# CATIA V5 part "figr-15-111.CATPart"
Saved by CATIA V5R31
Part number: Part1
Bounding box of the stored display mesh (mm): x 0.737 to 206.429, y 0 to 112.04, z -6 to 2
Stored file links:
  D:\PROJECTS\Project 2021\US EDITION\CATIA V5 6R 2021\Resources\Part Files\c15_catia_v5_6r2021_prt\figr-15-111.CATPart
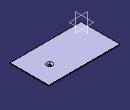
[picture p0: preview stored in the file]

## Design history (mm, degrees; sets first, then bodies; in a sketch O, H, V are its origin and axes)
SheetMetalParameters1: Thickness 2, BendRadius 4, KFactor 0.400515 {= log(min(100,max(20*SheetMetalParameters1.BendRadius,SheetMetalParameters1.Thickness)/SheetMetalParameters1.Thickness))/log(100)/2}, ReliefRadialLength 1, ReliefAxialLength 2, MinimumBendRadius 0
Body1 (main body)
  Sketch1 on xy-plane, origin (0, 0, 0), H (1, 0, 0), V (0, 1, 0)
    line L1 (0.7372, 112.0403) -> (206.4285, 112.0403)
    line L2 (206.4285, 112.0403) -> (206.4285, 0)
    line L3 (206.4285, 0) -> (0.7372, 0)
    line L4 (0.7372, 0) -> (0.7372, 112.0403)
    horizontal: L1 H, L3 H
    vertical: L2 V, L4 V
  Wall1: Thickness 2, Profile Sketch1, OffsetValue 0
  Sketch2 on face of Wall1, origin (152.409, 60.7083, 2), H (1, 0, 0), V (0, 1, 0)
    point P1 (0, 0)
  d_Stamp1: KFacteur 0.400515 {= SheetMetalParameters1.KFactor}, NewRoot_AttribNormalisation "No Standard", Stamp_FilletActivity true, Stamp_FilletRadius 2, Stamp_IntersectFilletRadius 2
